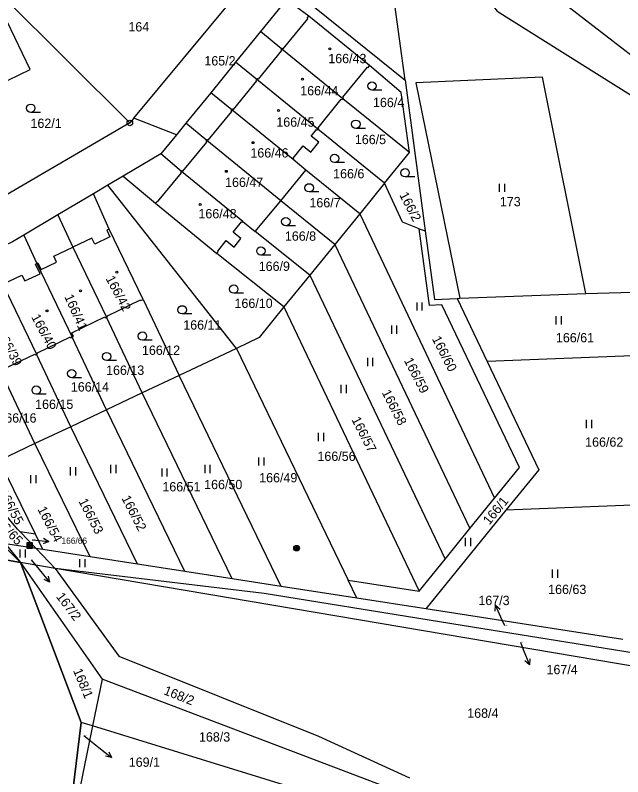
# Model space of a CAD drawing. Extents: x -737240 to -735272, y -1119606 to -1117878.
# Drawn here: x -736674.7 to -736563.9, y -1119214.7 to -1119075.8 of the extents above; entities that cross this region are included whole.
import ezdxf

# ---------------------------------------------------------------- set-up
doc = ezdxf.new("R2010")
doc.units = 0
for name, color, linetype in [('Level 1', 7, 'Continuous'), ('Level 13', 7, 'Continuous'), ('Level 16', 7, 'Continuous'), ('Level 18', 7, 'Continuous'), ('Level 19', 7, 'Continuous'), ('Level 25', 7, 'Continuous'), ('Level 4', 7, 'Continuous')]:
    doc.layers.add(name, color=color, linetype=linetype)

msp = doc.modelspace()

# ---------------------------------------------------------------- linework, layer by layer
at = {"layer": 'Level 1'}
for p, q in [((-736603.61, -1119087.67), (-736609.04, -1119046.89)), ((-736682.24, -1119067.06), (-736653.77, -1119095.47)), ((-736653.07, -1119094.62), (-736632.85, -1119070.25)), ((-736624.13, -1119071.09), (-736603.61, -1119087.67)), ((-736625.42, -1119073.22), (-736629.94, -1119078.78)), ((-736621.17, -1119076.03), (-736625.21, -1119072.96)), ((-736550.06, -1119092.7), (-736575.73, -1119072.8)), ((-736610.06, -1119085.02), (-736621.17, -1119076.03)), ((-736629.94, -1119078.78), (-736634.48, -1119084.36)), ((-736626.09, -1119082.03), (-736629.94, -1119078.78)), ((-736614.97, -1119091.05), (-736626.09, -1119082.03)), ((-736634.48, -1119084.36), (-736639.02, -1119089.95)), ((-736630.61, -1119087.55), (-736634.48, -1119084.36)), ((-736619.48, -1119096.6), (-736630.61, -1119087.55)), ((-736603.61, -1119087.67), (-736599.95, -1119115.16)), ((-736639.02, -1119089.95), (-736643.57, -1119095.53)), ((-736635.15, -1119093.08), (-736639.02, -1119089.95)), ((-736602.78, -1119100.86), (-736614.97, -1119091.05)), ((-736624, -1119102.16), (-736635.15, -1119093.08)), ((-736653.77, -1119095.47), (-736678.62, -1119109.93)), ((-736653.07, -1119094.62), (-736653.77, -1119095.47)), ((-736645.28, -1119097.63), (-736653.07, -1119094.62)), ((-736643.57, -1119095.53), (-736645.28, -1119097.63)), ((-736639.73, -1119098.68), (-736643.57, -1119095.53)), ((-736607.33, -1119106.45), (-736619.48, -1119096.6)), ((-736645.28, -1119097.63), (-736648.11, -1119101.12)), ((-736607.33, -1119106.45), (-736602.78, -1119100.86)), ((-736648.11, -1119101.12), (-736654.99, -1119105.19)), ((-736644.34, -1119104.31), (-736648.11, -1119101.12)), ((-736621.66, -1119104.06), (-736624, -1119102.16)), ((-736654.99, -1119105.19), (-736657.75, -1119106.83)), ((-736654.99, -1119105.19), (-736649.1, -1119110.11)), ((-736633.18, -1119113.44), (-736644.34, -1119104.31)), ((-736626.23, -1119109.69), (-736621.66, -1119104.06)), ((-736611.87, -1119112.03), (-736621.66, -1119104.06)), ((-736607.33, -1119106.45), (-736611.87, -1119112.03)), ((-736657.75, -1119106.83), (-736660.41, -1119108.4)), ((-736634.35, -1119136.57), (-736657.75, -1119106.83)), ((-736660.41, -1119108.4), (-736666.89, -1119112.24)), ((-736657.52, -1119114.81), (-736660.41, -1119108.4)), ((-736649.1, -1119110.11), (-736637.92, -1119119.27)), ((-736630.93, -1119115.24), (-736626.23, -1119109.69)), ((-736616.41, -1119117.62), (-736626.23, -1119109.69)), ((-736611.87, -1119112.03), (-736616.41, -1119117.62)), ((-736611.87, -1119112.03), (-736587.27, -1119163.85)), ((-736666.89, -1119112.24), (-736673.11, -1119115.93)), ((-736666.89, -1119112.24), (-736664.19, -1119118.14)), ((-736633.18, -1119113.44), (-736630.93, -1119115.24)), ((-736651.32, -1119127.65), (-736657.52, -1119114.81)), ((-736601.02, -1119114.75), (-736599.95, -1119115.16)), ((-736673.11, -1119115.93), (-736670.74, -1119121.08)), ((-736620.95, -1119123.2), (-736630.93, -1119115.24)), ((-736616.41, -1119117.62), (-736620.95, -1119123.2)), ((-736616.41, -1119117.62), (-736591.79, -1119169.43)), ((-736664.19, -1119118.14), (-736658.03, -1119130.86)), ((-736625.68, -1119129.02), (-736637.92, -1119119.27)), ((-736670.74, -1119121.08), (-736664.27, -1119134.51)), ((-736620.95, -1119123.2), (-736625.68, -1119129.02)), ((-736620.95, -1119123.2), (-736596.31, -1119175.01)), ((-736676.92, -1119124.85), (-736670.76, -1119137.62)), ((-736594.12, -1119127.45), (-736593.59, -1119127.42)), ((-736593.59, -1119127.42), (-736570.65, -1119126.56)), ((-736651.32, -1119127.65), (-736644.76, -1119141.48)), ((-736594.12, -1119127.45), (-736588.63, -1119138.96)), ((-736625.68, -1119129.02), (-736601.02, -1119180.82)), ((-736651.54, -1119144.68), (-736658.03, -1119130.86)), ((-736658.05, -1119147.76), (-736664.27, -1119134.51)), ((-736634.35, -1119136.57), (-736644.76, -1119141.48)), ((-736634.35, -1119136.57), (-736613.96, -1119178.82)), ((-736664.55, -1119150.84), (-736670.76, -1119137.62)), ((-736557.78, -1119137.77), (-736588.63, -1119138.96)), ((-736671.06, -1119153.92), (-736677.26, -1119140.74)), ((-736644.76, -1119141.48), (-736651.54, -1119144.68)), ((-736626.16, -1119179.98), (-736644.76, -1119141.48)), ((-736651.54, -1119144.68), (-736658.05, -1119147.76)), ((-736635.14, -1119178.58), (-736651.54, -1119144.68)), ((-736658.05, -1119147.76), (-736664.55, -1119150.84)), ((-736643.76, -1119177.25), (-736658.05, -1119147.76)), ((-736664.55, -1119150.84), (-736671.06, -1119153.92)), ((-736652.36, -1119175.92), (-736664.55, -1119150.84)), ((-736671.06, -1119153.92), (-736677.57, -1119157)), ((-736661, -1119174.59), (-736671.06, -1119153.92)), ((-736670.98, -1119170.46), (-736677.57, -1119157)), ((-736591.79, -1119169.43), (-736587.27, -1119163.85)), ((-736585.21, -1119166.05), (-736599.79, -1119184.05)), ((-736559.01, -1119165.04), (-736585.21, -1119166.05)), ((-736673.78, -1119170.02), (-736670.84, -1119173.07)), ((-736670.98, -1119170.46), (-736673.78, -1119170.02)), ((-736669.61, -1119173.26), (-736670.98, -1119170.46)), ((-736596.31, -1119175.01), (-736591.79, -1119169.43)), ((-736673.69, -1119175.61), (-736693.71, -1119172)), ((-736677.21, -1119172.08), (-736673.69, -1119175.61)), ((-736670.84, -1119173.07), (-736676.42, -1119172.2)), ((-736676.42, -1119172.2), (-736673.69, -1119175.61)), ((-736670.84, -1119173.07), (-736667.36, -1119176.68)), ((-736669.61, -1119173.26), (-736670.84, -1119173.07)), ((-736661, -1119174.59), (-736669.61, -1119173.26)), ((-736652.36, -1119175.92), (-736661, -1119174.59)), ((-736662.64, -1119204.74), (-736673.69, -1119175.61)), ((-736673.69, -1119175.61), (-736658.83, -1119196.84)), ((-736667.36, -1119176.68), (-736673.69, -1119175.61)), ((-736643.76, -1119177.25), (-736652.36, -1119175.92)), ((-736601.02, -1119180.82), (-736596.31, -1119175.01)), ((-736560.76, -1119194.73), (-736667.36, -1119176.68)), ((-736635.14, -1119178.58), (-736643.76, -1119177.25)), ((-736626.16, -1119179.98), (-736635.14, -1119178.58)), ((-736612.39, -1119182.1), (-736626.16, -1119179.98)), ((-736613.96, -1119178.82), (-736601.02, -1119180.82)), ((-736612.39, -1119182.1), (-736613.96, -1119178.82)), ((-736599.79, -1119184.05), (-736612.39, -1119182.1)), ((-736563.9, -1119189.61), (-736599.79, -1119184.05)), ((-736658.83, -1119196.84), (-736660.57, -1119205.38)), ((-736665.92, -1119231.67), (-736662.64, -1119204.74)), ((-736660.57, -1119205.38), (-736662.64, -1119204.74)), ((-736660.57, -1119205.38), (-736665.92, -1119231.67))]:
    msp.add_line(p, q, dxfattribs=at)
for points in [[(-736609.04, -1119046.89), (-736586.82, -1119075.1), (-736556.31, -1119094.26), (-736539.53, -1119110.19), (-736525.82, -1119129.35), (-736521.63, -1119146.17)], [(-736671.93, -1119085.75), (-736676.15, -1119076.95), (-736678.31, -1119077.99), (-736678.72, -1119077.1), (-736688.69, -1119081.79), (-736684.01, -1119091.54), (-736671.93, -1119085.75)], [(-736614.97, -1119091.05), (-736614.82, -1119090.87), (-736614.94, -1119090.78), (-736610.47, -1119085.28), (-736610.35, -1119085.37), (-736610.06, -1119085.02)], [(-736602.78, -1119100.86), (-736604.33, -1119089.93), (-736610.06, -1119085.02)], [(-736570.65, -1119126.56), (-736578.53, -1119087.11), (-736601.63, -1119088.15), (-736593.59, -1119127.42)], [(-736619.48, -1119096.6), (-736619.33, -1119096.42), (-736619.45, -1119096.33), (-736615.22, -1119091.13), (-736615.11, -1119091.22), (-736614.97, -1119091.05)], [(-736624, -1119102.16), (-736623.86, -1119101.98), (-736623.97, -1119101.89), (-736622.16, -1119099.66), (-736620.79, -1119100.78), (-736619.32, -1119098.97), (-736620.69, -1119097.85), (-736619.74, -1119096.68), (-736619.62, -1119096.77), (-736619.48, -1119096.6)], [(-736626.23, -1119109.69), (-736628.58, -1119107.79), (-736639.73, -1119098.68)], [(-736601.02, -1119114.75), (-736604.06, -1119113.57), (-736607.33, -1119106.45)], [(-736637.92, -1119119.27), (-736637.64, -1119118.92), (-736637.75, -1119118.83), (-736636.2, -1119116.92), (-736634.77, -1119118.09), (-736633.53, -1119116.55), (-736634.96, -1119115.39), (-736633.43, -1119113.52), (-736633.32, -1119113.61), (-736633.18, -1119113.44)], [(-736587.27, -1119163.85), (-736582.75, -1119158.27), (-736596.9, -1119128.6), (-736599.12, -1119128.72), (-736601.02, -1119114.75)], [(-736673.11, -1119115.93), (-736675.14, -1119117.13), (-736679.52, -1119119.2)], [(-736599.95, -1119115.16), (-736598.25, -1119127.67), (-736594.12, -1119127.45)], [(-736570.65, -1119126.56), (-736562.16, -1119126.31), (-736557.82, -1119137.28), (-736557.78, -1119137.77)], [(-736658.03, -1119130.86), (-736657.8, -1119130.75), (-736657.87, -1119130.62), (-736651.83, -1119127.73), (-736651.77, -1119127.86), (-736651.32, -1119127.65)], [(-736625.68, -1119129.02), (-736630.22, -1119134.6), (-736634.35, -1119136.57)], [(-736664.27, -1119134.51), (-736664.04, -1119134.41), (-736664.37, -1119133.73), (-736658.34, -1119130.84), (-736658.27, -1119130.98), (-736658.03, -1119130.86)], [(-736670.76, -1119137.62), (-736670.53, -1119137.51), (-736670.6, -1119137.38), (-736664.57, -1119134.49), (-736664.5, -1119134.63), (-736664.27, -1119134.51)], [(-736677.26, -1119140.74), (-736677.04, -1119140.63), (-736677.1, -1119140.49), (-736671.06, -1119137.6), (-736671, -1119137.74), (-736670.76, -1119137.62)], [(-736588.63, -1119138.96), (-736579.23, -1119158.68), (-736585.21, -1119166.05)], [(-736673.78, -1119170.02), (-736674.23, -1119169.55), (-736682.7, -1119159.43)], [(-736667.06, -1119249.16), (-736691.06, -1119241.83), (-736704.74, -1119235.5), (-736723.73, -1119226.81), (-736743.15, -1119221.74), (-736738.77, -1119203.51), (-736735.65, -1119190.52), (-736731.56, -1119173.9), (-736724.99, -1119172.93), (-736717.53, -1119171.82), (-736710.06, -1119170.71), (-736704.98, -1119169.96), (-736702.42, -1119170.42), (-736693.71, -1119172), (-736673.69, -1119175.61), (-736662.64, -1119204.74), (-736665.92, -1119231.67)], [(-736667.36, -1119176.68), (-736655.78, -1119192.66), (-736619.36, -1119207.27), (-736602.8, -1119214.86)], [(-736560.3, -1119192.36), (-736591.29, -1119187.37), (-736629.31, -1119181.27), (-736667.36, -1119176.68)], [(-736570.67, -1119237.72), (-736571.87, -1119236.16), (-736588.24, -1119223.64), (-736658.83, -1119196.84)], [(-736570.67, -1119237.72), (-736581.11, -1119229.95), (-736660.57, -1119205.38)]]:
    msp.add_lwpolyline(points, dxfattribs=at)
at = {"layer": 'Level 13'}
msp.add_lwpolyline([(-736665.92, -1119231.67), (-736662.64, -1119204.74), (-736673.69, -1119175.61), (-736693.71, -1119172), (-736702.42, -1119170.42), (-736704.98, -1119169.96), (-736710.06, -1119170.71), (-736717.53, -1119171.82), (-736724.99, -1119172.93), (-736731.56, -1119173.9), (-736735.65, -1119190.52), (-736738.77, -1119203.51), (-736743.15, -1119221.74)], dxfattribs=at)
msp.add_lwpolyline([(-736665.92, -1119231.67), (-736662.64, -1119204.74), (-736673.69, -1119175.61), (-736693.71, -1119172), (-736702.42, -1119170.42), (-736704.98, -1119169.96), (-736710.06, -1119170.71), (-736717.53, -1119171.82), (-736724.99, -1119172.93), (-736731.56, -1119173.9), (-736735.65, -1119190.52), (-736738.77, -1119203.51), (-736743.15, -1119221.74)], dxfattribs=at)
at = {"layer": 'Level 16'}
for points in [[(-736671.6, -1119171.47), (-736671.53, -1119171.48), (-736668.544, -1119171.773)], [(-736669.491, -1119171.178), (-736668.544, -1119171.773), (-736669.588, -1119172.173)], [(-736671.78, -1119175.1), (-736670.31, -1119176.86), (-736668.387, -1119179.163)], [(-736668.644, -1119178.075), (-736668.387, -1119179.163), (-736669.412, -1119178.716)], [(-736587.158, -1119184.492), (-736587.113, -1119183.375), (-736586.246, -1119184.081)], [(-736585.42, -1119187.12), (-736585.88, -1119186.11), (-736587.113, -1119183.375)], [(-736582.57, -1119190.15), (-736582.05, -1119191.47), (-736580.944, -1119194.259)], [(-736580.848, -1119193.145), (-736580.944, -1119194.259), (-736581.777, -1119193.513)], [(-736662.17, -1119207.16), (-736659.45, -1119209.3), (-736657.091, -1119211.153)], [(-736657.568, -1119210.142), (-736657.091, -1119211.153), (-736658.186, -1119210.929)]]:
    msp.add_lwpolyline(points, dxfattribs=at)
at = {"layer": 'Level 25'}
for p, q in [((-736607.848, -1119089.48), (-736609.63, -1119089.48)), ((-736670.048, -1119093.54), (-736671.83, -1119093.54)), ((-736610.788, -1119096.45), (-736612.57, -1119096.45)), ((-736614.668, -1119102.69), (-736616.45, -1119102.69)), ((-736601.808, -1119105.31), (-736603.59, -1119105.31)), ((-736586.427, -1119106.545), (-736586.427, -1119108.045)), ((-736585.405, -1119108.045), (-736585.405, -1119106.545)), ((-736619.298, -1119108.05), (-736621.08, -1119108.05)), ((-736623.548, -1119114.21), (-736625.33, -1119114.21)), ((-736628.098, -1119119.57), (-736629.88, -1119119.57)), ((-736633.048, -1119126.51), (-736634.83, -1119126.51)), ((-736601.477, -1119128.175), (-736601.477, -1119129.675)), ((-736600.455, -1119129.675), (-736600.455, -1119128.175)), ((-736642.448, -1119130.29), (-736644.23, -1119130.29)), ((-736576.117, -1119130.685), (-736576.117, -1119132.185)), ((-736575.095, -1119132.185), (-736575.095, -1119130.685)), ((-736606.097, -1119132.385), (-736606.097, -1119133.885)), ((-736605.075, -1119133.885), (-736605.075, -1119132.385)), ((-736649.698, -1119135.08), (-736651.48, -1119135.08)), ((-736610.467, -1119138.295), (-736610.467, -1119139.795)), ((-736609.445, -1119139.795), (-736609.445, -1119138.295)), ((-736656.208, -1119138.8), (-736657.99, -1119138.8)), ((-736662.588, -1119141.92), (-736664.37, -1119141.92)), ((-736615.327, -1119143.235), (-736615.327, -1119144.735)), ((-736614.305, -1119144.735), (-736614.305, -1119143.235)), ((-736669.048, -1119144.93), (-736670.83, -1119144.93)), ((-736570.577, -1119149.605), (-736570.577, -1119151.105)), ((-736569.555, -1119151.105), (-736569.555, -1119149.605)), ((-736619.457, -1119151.985), (-736619.457, -1119153.485)), ((-736618.435, -1119153.485), (-736618.435, -1119151.985)), ((-736630.307, -1119156.435), (-736630.307, -1119157.935)), ((-736629.285, -1119157.935), (-736629.285, -1119156.435)), ((-736657.297, -1119157.815), (-736657.297, -1119159.315)), ((-736656.275, -1119159.315), (-736656.275, -1119157.815)), ((-736640.127, -1119157.815), (-736640.127, -1119159.315)), ((-736639.105, -1119159.315), (-736639.105, -1119157.815)), ((-736664.647, -1119158.225), (-736664.647, -1119159.725)), ((-736663.625, -1119159.725), (-736663.625, -1119158.225)), ((-736647.957, -1119158.435), (-736647.957, -1119159.935)), ((-736646.935, -1119159.935), (-736646.935, -1119158.435)), ((-736671.857, -1119159.665), (-736671.857, -1119161.165)), ((-736670.835, -1119161.165), (-736670.835, -1119159.665)), ((-736592.637, -1119171.105), (-736592.637, -1119172.605)), ((-736591.615, -1119172.605), (-736591.615, -1119171.105)), ((-736673.797, -1119173.205), (-736673.797, -1119174.705)), ((-736672.775, -1119174.705), (-736672.775, -1119173.205)), ((-736662.957, -1119174.975), (-736662.957, -1119176.475)), ((-736661.935, -1119176.475), (-736661.935, -1119174.975)), ((-736576.767, -1119176.895), (-736576.767, -1119178.395)), ((-736575.745, -1119178.395), (-736575.745, -1119176.895))]:
    msp.add_line(p, q, dxfattribs=at)
for points in [[(-736671.52, -1119172), (-736672.52, -1119172), (-736672.52, -1119173), (-736671.52, -1119173)], [(-736671.72, -1119172.2), (-736672.32, -1119172.2), (-736672.32, -1119172.8), (-736671.72, -1119172.8)], [(-736672.12, -1119172.6), (-736671.92, -1119172.6), (-736671.92, -1119172.4), (-736672.12, -1119172.4)]]:
    msp.add_lwpolyline(points, close=True, dxfattribs=at)
for centre, major_axis, ratio in [((-736617.3, -1119081.98), (0.18, 0), 0.9848078), ((-736622.28, -1119087.47), (0.18, 0), 0.9848078), ((-736609.63, -1119088.724), (0.764, 0), 0.9894236), ((-736671.83, -1119092.784), (0.764, 0), 0.9894236), ((-736626.65, -1119093.2), (0.18, 0), 0.9848078), ((-736653.77, -1119095.47), (0.516, 0), 0.9848078), ((-736653.77, -1119095.47), (0.0375, 0), 0.9848078), ((-736612.57, -1119095.694), (0.764, 0), 0.9894236), ((-736631.32, -1119099.06), (0.18, 0), 0.9848078), ((-736616.45, -1119101.934), (0.764, 0), 0.9894236), ((-736603.59, -1119104.554), (0.764, 0), 0.9894236), ((-736636.18, -1119104.29), (0.18, 0), 0.9848078), ((-736621.08, -1119107.294), (0.764, 0), 0.9894236), ((-736640.97, -1119110.34), (0.18, 0), 0.9848078), ((-736625.33, -1119113.454), (0.764, 0), 0.9894236), ((-736629.88, -1119118.814), (0.764, 0), 0.9894236), ((-736656.14, -1119122.65), (0.18, 0), 0.9848078), ((-736662.77, -1119126.07), (0.18, 0), 0.9848078), ((-736634.83, -1119125.754), (0.764, 0), 0.9894236), ((-736644.23, -1119129.534), (0.764, 0), 0.9894236), ((-736668.87, -1119129.72), (0.18, 0), 0.9848078), ((-736651.48, -1119134.324), (0.764, 0), 0.9894236), ((-736657.99, -1119138.044), (0.764, 0), 0.9894236), ((-736664.37, -1119141.164), (0.764, 0), 0.9894236), ((-736670.83, -1119144.174), (0.764, 0), 0.9894236), ((-736623.37, -1119172.99), (0.516, 0), 0.9848078), ((-736623.37, -1119172.99), (0.309, 0), 0.9848078), ((-736623.37, -1119172.99), (0.155, 0), 0.9848078)]:
    msp.add_ellipse(centre, major_axis=major_axis, ratio=ratio, dxfattribs=at)
at = {"layer": 'Level 4'}
for points in [[(-736626.09, -1119082.03), (-736625.94, -1119081.85), (-736625.82, -1119081.95), (-736621.34, -1119076.48), (-736621.46, -1119076.38), (-736621.17, -1119076.03)], [(-736626.09, -1119082.03), (-736626.23, -1119082.2), (-736626.11, -1119082.29), (-736630.35, -1119087.47), (-736630.47, -1119087.37), (-736630.61, -1119087.55)], [(-736635.15, -1119093.08), (-736635, -1119092.91), (-736634.88, -1119093), (-736630.64, -1119087.82), (-736630.75, -1119087.72), (-736630.61, -1119087.55)], [(-736639.73, -1119098.68), (-736639.59, -1119098.51), (-736639.47, -1119098.6), (-736635.17, -1119093.35), (-736635.29, -1119093.25), (-736635.15, -1119093.08)], [(-736644.34, -1119104.31), (-736644.2, -1119104.13), (-736644.08, -1119104.23), (-736639.76, -1119098.95), (-736639.87, -1119098.85), (-736639.73, -1119098.68)], [(-736649.1, -1119110.11), (-736648.81, -1119109.76), (-736648.7, -1119109.86), (-736644.37, -1119104.57), (-736644.48, -1119104.48), (-736644.34, -1119104.31)], [(-736657.52, -1119114.81), (-736657.98, -1119115.03), (-736657.41, -1119116.24), (-736660.18, -1119117.55), (-736660.69, -1119116.48), (-736664.19, -1119118.14)], [(-736670.74, -1119121.08), (-736670.51, -1119120.97), (-736669.93, -1119122.19), (-736667.14, -1119120.86), (-736667.65, -1119119.78), (-736664.19, -1119118.14)], [(-736676.92, -1119124.85), (-736673.44, -1119123.2), (-736672.92, -1119124.28), (-736670.11, -1119122.99), (-736670.97, -1119121.19), (-736670.74, -1119121.08)]]:
    msp.add_lwpolyline(points, dxfattribs=at)

# ---------------------------------------------------------------- texts
at = {"layer": 'Level 16'}
for s, height, p in [('166/66', 1.14, (-736666.23, -1119172.19)), ('167/3', 1.7, (-736590.235, -1119183.37)), ('167/4', 1.7, (-736577.815, -1119195.96)), ('169/1', 1.7, (-736653.965, -1119212.85))]:
    msp.add_text(s, height=height, dxfattribs=at).set_placement(p)
msp.add_text('167/2', height=1.7, rotation=307.026, dxfattribs=at).set_placement((-736667.288, -1119181.85))
at = {"layer": 'Level 18'}
for s, height, p in [('164', 1.7, (-736654.035, -1119078.79)), ('165/2', 1.7, (-736640.185, -1119084.99)), ('166/4', 1.7, (-736609.445, -1119092.58)), ('162/1', 1.7, (-736671.875, -1119096.38)), ('166/5', 1.7, (-736612.745, -1119099.33)), ('166/6', 1.7, (-736616.705, -1119105.56)), ('166/7', 1.7, (-736621.035, -1119110.85)), ('173', 1.7, (-736586.315, -1119110.66)), ('166/8', 1.7, (-736625.505, -1119116.94)), ('166/9', 1.7, (-736630.275, -1119122.44)), ('166/10', 1.7, (-736634.69, -1119129.19)), ('166/11', 1.7, (-736644.03, -1119133.14)), ('166/61', 1.7, (-736576.1, -1119135.46)), ('166/12', 1.7, (-736651.56, -1119137.75)), ('166/13', 1.7, (-736658.1, -1119141.39)), ('166/14', 1.7, (-736664.52, -1119144.43)), ('166/15', 1.7, (-736671.03, -1119147.6)), ('166/16', 1.7, (-736677.74, -1119150.1)), ('166/62', 1.7, (-736570.77, -1119154.49)), ('166/56', 1.7, (-736619.57, -1119157.08)), ('166/49', 1.7, (-736630.19, -1119160.99)), ('166/50', 1.7, (-736640.22, -1119162.23)), ('166/51', 1.7, (-736647.84, -1119162.64)), ('166/66', 0.1, (-736671.45, -1119171.47)), ('167/2', 0.1, (-736671.655, -1119175.1)), ('166/63', 1.7, (-736577.51, -1119181.35)), ('167/3', 0.1, (-736585.295, -1119187.12)), ('167/4', 0.1, (-736582.445, -1119190.15)), ('168/4', 1.7, (-736592.265, -1119203.91)), ('168/3', 1.7, (-736641.165, -1119208.25)), ('169/1', 0.1, (-736662.045, -1119207.16))]:
    msp.add_text(s, height=height, dxfattribs=at).set_placement(p)
for s, rotation, p in [('166/2', 297.18666, (-736604.689, -1119108.58)), ('166/60', 297.18666, (-736598.745, -1119134.818)), ('166/59', 297.18666, (-736603.845, -1119138.768)), ('166/58', 297.18666, (-736607.895, -1119144.608)), ('166/57', 297.18666, (-736613.405, -1119149.548)), ('166/55', 297.84051, (-736677.759, -1119162.745)), ('166/52', 297.18666, (-736655.335, -1119163.878)), ('166/53', 297.18666, (-736663.165, -1119164.428)), ('166/1', 50.72895, (-736588.24, -1119168.87)), ('166/54', 297.18666, (-736670.645, -1119165.878)), ('166/65', 313.43148, (-736679.097, -1119167.532)), ('168/1', 292.65993, (-736664.141, -1119195.311)), ('168/2', 338.34114, (-736647.735, -1119199.584))]:
    msp.add_text(s, height=1.7, rotation=rotation, dxfattribs=at).set_placement(p)
at = {"layer": 'Level 19'}
for s, p in [('166/43', (-736617.595, -1119084.57)), ('166/44', (-736622.705, -1119090.43)), ('166/45', (-736627.065, -1119096.16)), ('166/46', (-736631.795, -1119101.77)), ('166/47', (-736636.405, -1119107.13)), ('166/48', (-736641.265, -1119112.86))]:
    msp.add_text(s, height=1.7, dxfattribs=at).set_placement(p)
for s, rotation, p in [('166/42', 298.00161, (-736658.22, -1119123.84)), ('166/41', 293.60412, (-736665.74, -1119127.12)), ('166/40', 297.84159, (-736671.78, -1119130.84)), ('166/39', 297.84159, (-736678.03, -1119133.82))]:
    msp.add_text(s, height=1.7, rotation=rotation, dxfattribs=at).set_placement(p)

doc.saveas('drawing.dxf')
